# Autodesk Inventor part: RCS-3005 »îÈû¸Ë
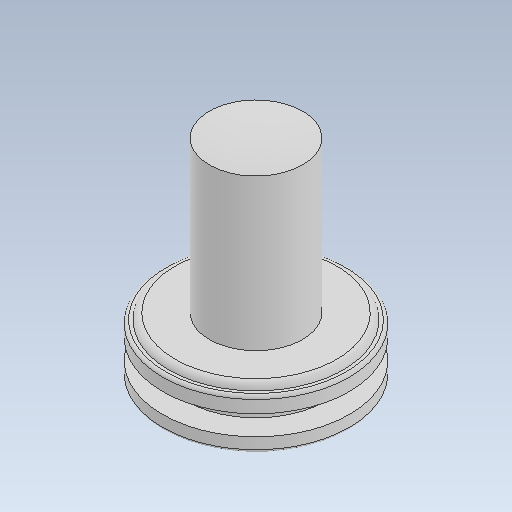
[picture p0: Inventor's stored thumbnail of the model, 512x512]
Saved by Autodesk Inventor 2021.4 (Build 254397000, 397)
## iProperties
Created: 2019-12
Part Number: RCS-3005 »îÈû¸Ë
Material: Ogólny
Document SubType Name: Modeling
Designer: user
Density: 1 g/cm^3
Appearance: Domyślna
Author: user
Revision Number: ÈÎºÎ
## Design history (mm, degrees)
feature "Ðý×ª1"
node "Bryła1"
